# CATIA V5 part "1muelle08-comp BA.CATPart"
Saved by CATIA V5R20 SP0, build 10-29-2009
Part number: 1muelle08-comp BA
Revision: ANY
Definition: UNKNOWN
Nomenclature: 1muelle08-comp BA
Source: Unknown
Bounding box of the stored display mesh (mm): x -5.85 to 5.85, y -5.85 to 5.85, z -0.001 to 8.299
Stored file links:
  C:\Users\Utente\Desktop\IO LAVORO\3D X SITO CF\CUMSA\3D files BA\BA 081620\1muelle08-comp BA.CATPart
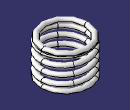
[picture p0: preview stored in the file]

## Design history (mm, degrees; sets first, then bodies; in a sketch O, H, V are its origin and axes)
Set1 "FacciaKO#NONE#528"
  DatumSurface1 "Sup528_1"
  DatumCurve1 "Crv528_1"
Set2 "FacciaKO#NONE#541"
  DatumSurface2 "Sup541_1"
  DatumCurve2 "Crv541_1"
Body1 "Cortar-Extruir1" (main body)
  Solid1: solid without history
